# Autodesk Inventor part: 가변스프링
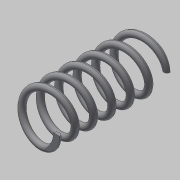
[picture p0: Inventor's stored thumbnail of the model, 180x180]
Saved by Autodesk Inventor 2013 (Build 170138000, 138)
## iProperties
Created: 2020-02
Part Number: 가변스프링
Material: 일반
Document SubType Name: Modeling
Designer: Administrator
Density: 1 g/cm^3
Mass: -0.0105754 g
Surface Area: 16.6087 cm^2
Volume: -0.0105754 cm^3
Author: Administrator
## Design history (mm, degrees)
sketch "스케치1"
  geometry: L1 (0, 0)-(7, 0); L2 (7, 0)-(7, 35.5); L3 (7, 35.5)-(0, 35.5); L4 (0, 35.5)-(0, 0); C1 r 1 at (7, 0)
  constraints: 8 end point, 2 parallel, 1 centre point, 1 coincident, 1 horizontal, 1 perpendicular
  dimensions: "d0" = 2 diameter of C1; "d2" = 14 diameter of L2 L4; "d3" = 35.5 distance of L1.end L2.end (derived)
feature "코일1" sketch "스케치1" pitch "d4" = 10; turns "d6" = 6; dims "d5" = 35.5 (= d3), "d7" = 0, angle "d8" = 90 deg, angle "d9" = 90 deg, "d10" = 0, "d11" = 0
sketch "스케치2"
  geometry: L1 (35.5, 9)-(0, 9); L2 (0, 9)-(0, -9); L3 (0, -9)-(35.5, -9); L4 (35.5, -9)-(35.5, 9); 2 further points
  constraints: 8 end point, 2 parallel, 1 coincident, 1 horizontal, 1 midpoint, 1 perpendicular
  dimensions: "d12" = 35.5 distance of L2.end L3.end (derived); "d14" = 18 distance of L3.end L1.start
extrude "돌출1" sketch "스케치2" stored distance "d15" = 18; taper "d16" = 0 deg
node "솔리드1"
